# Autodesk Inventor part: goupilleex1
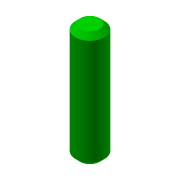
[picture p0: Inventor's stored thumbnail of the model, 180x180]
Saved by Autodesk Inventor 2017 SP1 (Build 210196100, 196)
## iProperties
Created: 2006-05
Part Number: goupilleex1
Document SubType Name: Modeling
Designer: Administrateur
Manufacturer: Standard
Standards Organization: Custom
Material: Acier, haute résistance, modérément allié
Mass: 0.64942 g
Surface Area: 1.21063 cm^2
Volume: 0.0827286 cm^3
Density: 7.85 g/cm^3
Appearance: Vert foncé
Author: Administrateur
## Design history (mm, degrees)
sketch "Esquisse1"
  geometry: C1 r 1.5 at (0, 0)
  constraints: 1 centre point
  dimensions: "d0" = 3 diameter of C1
extrude "Extrusion1" new body sketch "Esquisse1" distance "d1" = 12; taper "d2" = 0 deg
chamfer "Chanfrein1" distance "d3" = 0.5; stored, may be unused: second distance "d4" = 2, angle "d5" = 45 deg
node "Solide1"
node "Corps solides"
node "Corps surfaciques"
